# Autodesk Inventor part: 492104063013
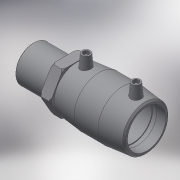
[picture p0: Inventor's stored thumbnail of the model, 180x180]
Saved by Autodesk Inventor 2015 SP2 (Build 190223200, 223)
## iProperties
Created: 2017-06
Part Number: 492104063013
Material: Generic
Description: PLASSON Male Transition Coupler 63 x 1.1/4"
Document SubType Name: Modeling
Designer: KIM
Mass: 334.629 g
Surface Area: 744.687 cm^2
Volume: 334.629 cm^3
Density: 1 g/cm^3
Appearance: Default
Author: KIM
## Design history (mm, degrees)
derived "492104.ipt"
feature "Solid1::492104.ipt"
tag "TaggingFeature1"
body "Solid1"
other parameters: "d0" = 117, "d1" = 63, "d2" = 82, "d3" = 57, "d4" = 39, "d5" = 73.8, "d6" = 59.85, "d7" = 63, "d8" = 168 deg, "d10" = 22.8, "d11" = 7.6, "d29" = 57, "d30" = 14, "d31" = 40.95, "d34" = 5 deg, "d41" = 4, "d42" = 14, "d43" = 0, "d48" = 3, "d49" = 0, "d57" = 48, "d58" = 41.91, "d59" = 33.528, "d60" = 32.4, "d61" = 82, "d62" = 0.8382, "d65" = 2.46, "d70" = 0.1, "d71" = 36, "d72" = 9, "d73" = 22.8, "d75" = 0, "d_" = 63, "L_" = 153, "L_1" = 57, "D_1" = 82, "A_" = 57, "d_2" = 12, "L_2" = 36, "D_" = 48, "R_" = 41.91
